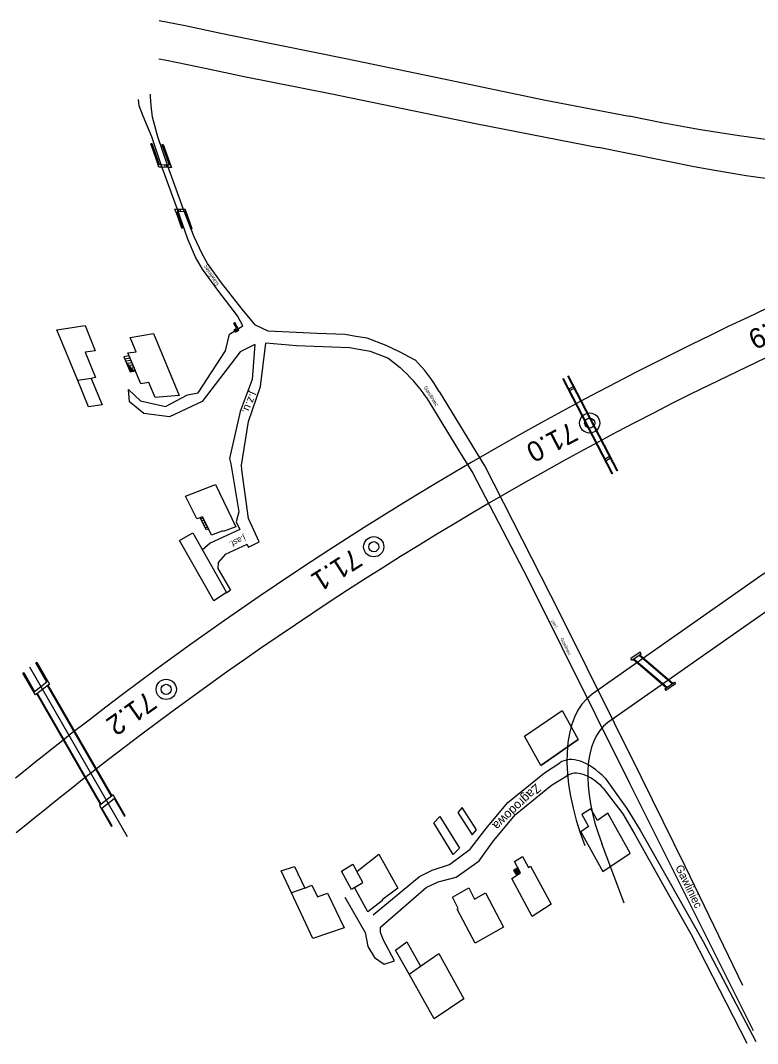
# Model space of a CAD drawing. Extents: x 6541740 to 6556805, y 5525233 to 5530361.
# Drawn here: x 6554814.6 to 6554888.2, y 5525643 to 5525745.1 of the extents above; entities that cross this region are included whole.
import ezdxf

# ---------------------------------------------------------------- set-up
doc = ezdxf.new("R2010")
doc.units = 0
for name, color, linetype in [('Default', 7, 'Continuous'), ('TOR_SCH-budynki', 7, 'Continuous'), ('TOR_SCH-hektometry', 7, 'Continuous'), ('TOR_SCH-obiekty projektowane', 7, 'Continuous'), ('TOR_SCH-przejazdy+drogi istniejace', 7, 'Continuous'), ('TOR_SCH-przejazdy+drogi projektowane', 7, 'Continuous'), ('TOR_SCH-tory i rozjazdy do rozbiorki', 7, 'Continuous'), ('TOR_SCH-tory projektowane', 7, 'Continuous')]:
    doc.layers.add(name, color=color, linetype=linetype)

# ---------------------------------------------------------------- blocks, each defined once
blk = doc.blocks.new('4010_1')
at = {"layer": 'Default'}
for radius in [0.75, 0.375]:
    blk.add_circle((0, 0), radius, dxfattribs=at)
blk = doc.blocks.new('POINT_DISPLAY')
at = {"layer": 'Default'}
blk.add_line((0, 0), (0, 0), dxfattribs=at)

msp = doc.modelspace()

# ---------------------------------------------------------------- linework, layer by layer
at = {"layer": 'TOR_SCH-budynki'}
for p, q in [((6554818.21, 5525714.25), (6554821.01, 5525714.68)), ((6554821.01, 5525714.68), (6554822.01, 5525712.18)), ((6554820.28, 5525709.22), (6554818.21, 5525714.25)), ((6554825.53, 5525713.5), (6554827.85, 5525713.88)), ((6554827.85, 5525713.88), (6554830.42, 5525707.7)), ((6554826.12, 5525712.08), (6554825.53, 5525713.5)), ((6554822.01, 5525712.18), (6554821.01, 5525712.03)), ((6554821.01, 5525712.03), (6554822.06, 5525709.49)), ((6554825.41, 5525711.66), (6554824.89, 5525711.58)), ((6554824.89, 5525711.58), (6554825.51, 5525710.07)), ((6554825.3, 5525711.95), (6554826.12, 5525712.08)), ((6554826.57, 5525708.88), (6554825.3, 5525711.95)), ((6554826.04, 5525710.16), (6554825.41, 5525711.66)), ((6554825.51, 5525711.44), (6554824.99, 5525711.35)), ((6554825.6, 5525711.21), (6554825.08, 5525711.12)), ((6554825.7, 5525710.98), (6554825.24, 5525710.9)), ((6554825.6, 5525710.09), (6554825.28, 5525710.87)), ((6554825.79, 5525710.75), (6554825.46, 5525710.7)), ((6554825.73, 5525710.11), (6554825.5, 5525710.66)), ((6554825.89, 5525710.52), (6554825.69, 5525710.49)), ((6554822.06, 5525709.49), (6554821.62, 5525709.42)), ((6554825.51, 5525710.07), (6554826.04, 5525710.16)), ((6554825.86, 5525710.13), (6554825.72, 5525710.45)), ((6554825.98, 5525710.29), (6554825.91, 5525710.28)), ((6554825.99, 5525710.15), (6554825.95, 5525710.24)), ((6554821.62, 5525709.42), (6554820.28, 5525709.22)), ((6554821.37, 5525706.57), (6554820.28, 5525709.22)), ((6554821.62, 5525709.42), (6554822.71, 5525706.77)), ((6554827.39, 5525709.02), (6554826.57, 5525708.88)), ((6554828.01, 5525707.51), (6554827.39, 5525709.02)), ((6554830.42, 5525707.7), (6554828.01, 5525707.51)), ((6554822.71, 5525706.77), (6554821.37, 5525706.57)), ((6554831.05, 5525697.67), (6554834.05, 5525698.83)), ((6554834.05, 5525698.83), (6554836.06, 5525694.61)), ((6554832.16, 5525695.39), (6554831.05, 5525697.67)), ((6554832.75, 5525695.61), (6554832.16, 5525695.39)), ((6554832.51, 5525695.52), (6554832.75, 5525695.61)), ((6554833.11, 5525694.29), (6554832.51, 5525695.52)), ((6554832.57, 5525695.41), (6554832.8, 5525695.5)), ((6554832.67, 5525695.19), (6554832.91, 5525695.28)), ((6554833.64, 5525693.77), (6554832.75, 5525695.61)), ((6554832.75, 5525695.61), (6554833.34, 5525694.38)), ((6554832.78, 5525694.96), (6554833.02, 5525695.05)), ((6554832.89, 5525694.74), (6554833.13, 5525694.83)), ((6554833, 5525694.51), (6554833.24, 5525694.6)), ((6554833.34, 5525694.38), (6554833.11, 5525694.29)), ((6554834.77, 5525694.2), (6554833.64, 5525693.77)), ((6554834.8, 5525694.14), (6554834.77, 5525694.2)), ((6554836.06, 5525694.61), (6554834.8, 5525694.14)), ((6554830.44, 5525693.22), (6554831.76, 5525694)), ((6554833.86, 5525687.21), (6554830.44, 5525693.22)), ((6554831.76, 5525694), (6554835.13, 5525688.03)), ((6554835.13, 5525688.03), (6554833.86, 5525687.21)), ((6554864.9, 5525673.69), (6554868.66, 5525676.25)), ((6554868.66, 5525676.25), (6554870.25, 5525673.37)), ((6554866.51, 5525670.76), (6554864.9, 5525673.69)), ((6554870.25, 5525673.37), (6554866.51, 5525670.76)), ((6554855.83, 5525665.05), (6554856.44, 5525665.68)), ((6554856.44, 5525665.68), (6554858.39, 5525662.52)), ((6554871.51, 5525666.45), (6554870.63, 5525665.87)), ((6554870.63, 5525665.87), (6554871.27, 5525664.68)), ((6554872.17, 5525665.27), (6554871.51, 5525666.45)), ((6554873.22, 5525666.01), (6554872.17, 5525665.27)), ((6554875.44, 5525662.02), (6554873.22, 5525666.01)), ((6554857.77, 5525661.88), (6554855.83, 5525665.05)), ((6554871.27, 5525664.68), (6554870.51, 5525664.14)), ((6554870.51, 5525664.14), (6554872.71, 5525660.18)), ((6554858.39, 5525662.52), (6554857.77, 5525661.88)), ((6554848.15, 5525660.18), (6554850.36, 5525661.92)), ((6554850.36, 5525661.92), (6554852.23, 5525658.54)), ((6554863.89, 5525661.17), (6554864.69, 5525661.68)), ((6554864.69, 5525661.68), (6554865.29, 5525660.59)), ((6554872.71, 5525660.18), (6554875.44, 5525662.02)), ((6554840.59, 5525660.25), (6554841.94, 5525660.67)), ((6554841.94, 5525660.67), (6554842.96, 5525658.51)), ((6554846.61, 5525660.21), (6554847.74, 5525660.93)), ((6554847.74, 5525660.93), (6554848.15, 5525660.18)), ((6554864.22, 5525660.57), (6554863.81, 5525660.31)), ((6554864.49, 5525660.07), (6554863.89, 5525661.17)), ((6554864.13, 5525660.52), (6554864.4, 5525660.01)), ((6554864.49, 5525660.07), (6554864.22, 5525660.57)), ((6554865.29, 5525660.59), (6554865.5, 5525660.72)), ((6554865.5, 5525660.72), (6554867.57, 5525656.93)), ((6554841.63, 5525658.05), (6554840.59, 5525660.25)), ((6554847.61, 5525658.39), (6554846.61, 5525660.21)), ((6554848.74, 5525659.1), (6554848.15, 5525660.18)), ((6554863.62, 5525659.5), (6554864.49, 5525660.07)), ((6554865.67, 5525655.7), (6554863.62, 5525659.5)), ((6554863.81, 5525660.31), (6554864.09, 5525659.81)), ((6554863.92, 5525660.38), (6554864.19, 5525659.87)), ((6554864.02, 5525660.45), (6554864.3, 5525659.94)), ((6554864.09, 5525659.81), (6554864.49, 5525660.07)), ((6554842.96, 5525658.51), (6554841.63, 5525658.05)), ((6554842.96, 5525658.51), (6554843.67, 5525658.82)), ((6554843.67, 5525658.82), (6554844.21, 5525657.65)), ((6554847.91, 5525658.58), (6554847.61, 5525658.39)), ((6554847.91, 5525658.58), (6554848.74, 5525659.1)), ((6554849.26, 5525656.17), (6554847.91, 5525658.58)), ((6554852.23, 5525658.54), (6554850.69, 5525657.36)), ((6554857.7, 5525657.61), (6554859.32, 5525658.56)), ((6554859.32, 5525658.56), (6554859.91, 5525657.43)), ((6554843.77, 5525653.51), (6554841.63, 5525658.05)), ((6554844.21, 5525657.65), (6554845.22, 5525658.03)), ((6554845.22, 5525658.03), (6554846.87, 5525654.57)), ((6554858.27, 5525656.51), (6554857.7, 5525657.61)), ((6554859.91, 5525657.43), (6554861.01, 5525658.07)), ((6554861.01, 5525658.07), (6554862.81, 5525654.64)), ((6554850.72, 5525657.3), (6554849.26, 5525656.17)), ((6554850.69, 5525657.36), (6554850.72, 5525657.3)), ((6554858.16, 5525656.42), (6554858.27, 5525656.51)), ((6554859.96, 5525653.03), (6554858.16, 5525656.42)), ((6554867.57, 5525656.93), (6554865.67, 5525655.7)), ((6554846.87, 5525654.57), (6554843.77, 5525653.51)), ((6554862.81, 5525654.64), (6554859.96, 5525653.03)), ((6554852.01, 5525652.35), (6554853.14, 5525653.18)), ((6554853.38, 5525649.94), (6554852.01, 5525652.35)), ((6554853.14, 5525653.18), (6554854.51, 5525650.74)), ((6554854.51, 5525650.74), (6554856.34, 5525652.01)), ((6554856.34, 5525652.01), (6554858.84, 5525647.48)), ((6554853.38, 5525649.94), (6554854.51, 5525650.74)), ((6554855.87, 5525645.47), (6554853.38, 5525649.94)), ((6554858.84, 5525647.48), (6554855.87, 5525645.47))]:
    msp.add_line(p, q, dxfattribs=at)
msp.add_lwpolyline([(6554858.23, 5525666.08), (6554859.66, 5525663.86), (6554860.1, 5525664.36), (6554858.66, 5525666.58)], close=True, dxfattribs=at)
at = {"layer": 'TOR_SCH-obiekty projektowane'}
for p, q in [((6554825.24, 5525663.66), (6554815.49, 5525680.57)), ((6554822.57, 5525666.86), (6554816.2, 5525677.91)), ((6554822.63, 5525666.9), (6554816.26, 5525677.95)), ((6554823.65, 5525667.71), (6554817.28, 5525678.76)), ((6554823.71, 5525667.75), (6554817.34, 5525678.8))]:
    msp.add_line(p, q, dxfattribs=at)
for points in [[(6554869.18, 5525709.66), (6554874.1, 5525700.19)], [(6554869.25, 5525709.7), (6554874.17, 5525700.23)], [(6554868.67, 5525709.4), (6554873.61, 5525699.9)], [(6554868.74, 5525709.43), (6554873.67, 5525699.93)], [(6554869.81, 5525708.6), (6554869.24, 5525708.3)], [(6554869.75, 5525708.72), (6554869.68, 5525708.69)], [(6554869.23, 5525708.46), (6554869.17, 5525708.43)], [(6554869.91, 5525708.43), (6554869.33, 5525708.13)], [(6554873.43, 5525701.64), (6554872.87, 5525701.31)], [(6554873.52, 5525701.47), (6554872.97, 5525701.13)], [(6554873.67, 5525699.93), (6554873.61, 5525699.9)], [(6554874.17, 5525700.23), (6554874.1, 5525700.19)], [(6554875.6, 5525681.27), (6554876.55, 5525681.93), (6554876.45, 5525682.1), (6554875.5, 5525681.44)], [(6554875.6, 5525681.27), (6554875.6, 5525681.27), (6554875.5, 5525681.44)], [(6554875.75, 5525681.37), (6554879.06, 5525678.53)], [(6554875.82, 5525681.42), (6554879.13, 5525678.59)], [(6554876.33, 5525681.77), (6554879.64, 5525678.94)], [(6554876.41, 5525681.83), (6554879.71, 5525678.99)], [(6554878.91, 5525678.43), (6554879.86, 5525679.1), (6554879.96, 5525678.92), (6554879.01, 5525678.26)], [(6554878.91, 5525678.43), (6554878.91, 5525678.43), (6554879.01, 5525678.26)]]:
    msp.add_lwpolyline(points, dxfattribs=at)
for points in [[(6554817.2, 5525679.13), (6554816.11, 5525681.01), (6554816.19, 5525681.07), (6554817.45, 5525678.89), (6554816.07, 5525677.81), (6554814.81, 5525679.99), (6554814.89, 5525680.06), (6554815.98, 5525678.17)], [(6554823.91, 5525667.48), (6554824.94, 5525665.7), (6554825.02, 5525665.76), (6554823.82, 5525667.84), (6554822.44, 5525666.76), (6554823.64, 5525664.68), (6554823.72, 5525664.74), (6554822.69, 5525666.52)]]:
    msp.add_lwpolyline(points, close=True, dxfattribs=at)
at = {"layer": 'TOR_SCH-przejazdy+drogi istniejace'}
for p, q in [((6554827.73, 5525732.82), (6554827.59, 5525732.82)), ((6554827.84, 5525732.11), (6554827.59, 5525732.82)), ((6554827.75, 5525732.77), (6554827.73, 5525732.82)), ((6554828.34, 5525731.03), (6554827.75, 5525732.77)), ((6554828.67, 5525732.78), (6554828.81, 5525732.78)), ((6554828.93, 5525732.07), (6554829.13, 5525731.88)), ((6554828.15, 5525731.61), (6554827.95, 5525731.79)), ((6554828.23, 5525731.37), (6554828.03, 5525731.55)), ((6554829.02, 5525731.8), (6554829.22, 5525731.62)), ((6554828.98, 5525730.71), (6554828.93, 5525730.49)), ((6554829.18, 5525730.71), (6554829.12, 5525730.48)), ((6554830.33, 5525726.27), (6554830.28, 5525726.04)), ((6554830.52, 5525726.28), (6554830.47, 5525726.04)), ((6554830.38, 5525725.52), (6554830.77, 5525724.44)), ((6554830.39, 5525725.13), (6554830.58, 5525724.96)), ((6554830.47, 5525724.89), (6554830.67, 5525724.71)), ((6554831.38, 5525725.27), (6554831.18, 5525725.45)), ((6554831.46, 5525725.01), (6554831.26, 5525725.2)), ((6554830.63, 5525724.44), (6554830.77, 5525724.44)), ((6554831.7, 5525724.33), (6554831.56, 5525724.34)), ((6554835.43, 5525713.82), (6554836.76, 5525714.65)), ((6554835.96, 5525714.99), (6554835.86, 5525714.91)), ((6554836.02, 5525714.89), (6554835.91, 5525714.95)), ((6554836.2, 5525714.58), (6554835.97, 5525714.72)), ((6554835.05, 5525712.15), (6554835.43, 5525713.82)), ((6554836.02, 5525714.04), (6554835.9, 5525714.26)), ((6554844.2, 5525713.9), (6554839.31, 5525714.13)), ((6554837.98, 5525712.79), (6554836.51, 5525712.08)), ((6554837.98, 5525712.79), (6554837.69, 5525709.32)), ((6554838.54, 5525708.6), (6554839.05, 5525712.93)), ((6554832.31, 5525707.96), (6554835.05, 5525712.15)), ((6554836.51, 5525712.08), (6554832.7, 5525707.11)), ((6554837.69, 5525709.32), (6554836.5, 5525706.1)), ((6554837.34, 5525705.1), (6554838.54, 5525708.6)), ((6554825.46, 5525707.07), (6554825.35, 5525708.32)), ((6554825.35, 5525708.32), (6554826.55, 5525707.19)), ((6554829.03, 5525706.6), (6554831.24, 5525707.78)), ((6554831.24, 5525707.78), (6554832.31, 5525707.96)), ((6554855.08, 5525707.55), (6554858.31, 5525702.25)), ((6554860.94, 5525700.7), (6554856.39, 5525708.1)), ((6554826.87, 5525705.91), (6554825.46, 5525707.07)), ((6554826.55, 5525707.19), (6554829.03, 5525706.6)), ((6554832.7, 5525707.11), (6554829.43, 5525705.57)), ((6554829.43, 5525705.57), (6554826.87, 5525705.91)), ((6554836.5, 5525706.1), (6554835.45, 5525701.41)), ((6554836.65, 5525700.75), (6554837.34, 5525705.1)), ((6554835.45, 5525701.41), (6554835.57, 5525700.87)), ((6554858.31, 5525702.25), (6554859.73, 5525699.95)), ((6554835.57, 5525700.87), (6554836.37, 5525696.08)), ((6554836.66, 5525700.29), (6554836.65, 5525700.75)), ((6554868.44, 5525685.92), (6554860.94, 5525700.7)), ((6554837.32, 5525695.44), (6554836.66, 5525700.29)), ((6554859.73, 5525699.95), (6554865.22, 5525689.42)), ((6554836.37, 5525696.08), (6554836.09, 5525695.08)), ((6554838.4, 5525693.11), (6554837.32, 5525695.44)), ((6554836.09, 5525695.08), (6554836.46, 5525694.34)), ((6554837.18, 5525692.84), (6554837.32, 5525692.56)), ((6554837.32, 5525692.56), (6554838.4, 5525693.11)), ((6554865.22, 5525689.42), (6554875.39, 5525669)), ((6554876.58, 5525669.58), (6554868.44, 5525685.92)), ((6554866.51, 5525670.76), (6554870.25, 5525673.37)), ((6554875.39, 5525669), (6554887.71, 5525644.33)), ((6554880.95, 5525660.72), (6554876.58, 5525669.58)), ((6554886.68, 5525648.8), (6554880.95, 5525660.72)), ((6554887.13, 5525643.01), (6554881.67, 5525653.67)), ((6554882.72, 5525653.19), (6554887.99, 5525643.21))]:
    msp.add_line(p, q, dxfattribs=at)
for points in [[(6554828.62, 5525730.72), (6554827.67, 5525733.52), (6554826.81, 5525735.58), (6554826.43, 5525736.62), (6554826.34, 5525737.25)], [(6554830.84, 5525726.29), (6554829.23, 5525730.71), (6554828.28, 5525733.53), (6554827.75, 5525735.49), (6554827.62, 5525736.66), (6554827.55, 5525737.55), (6554827.55, 5525737.78)], [(6554828.54, 5525730.5), (6554828.37, 5525730.5), (6554828.21, 5525731.04), (6554827.84, 5525732.11)], [(6554828.67, 5525732.78), (6554829.31, 5525731), (6554829.34, 5525730.91)], [(6554828.81, 5525732.78), (6554829.45, 5525731), (6554829.48, 5525730.9)], [(6554829.34, 5525730.91), (6554829.42, 5525730.7), (6554829.23, 5525730.71), (6554828.62, 5525730.72), (6554828.44, 5525730.73), (6554828.35, 5525731.02), (6554828.34, 5525731.03)], [(6554829.48, 5525730.9), (6554829.64, 5525730.47), (6554829.31, 5525730.48), (6554828.71, 5525730.49), (6554828.54, 5525730.5)], [(6554836.76, 5525714.65), (6554836.25, 5525715.67), (6554834.26, 5525718.22), (6554832.75, 5525720.33), (6554832.05, 5525721.53), (6554831.27, 5525723.31), (6554830.25, 5525726.27), (6554828.62, 5525730.72)], [(6554831.09, 5525726.13), (6554831.03, 5525726.29), (6554830.84, 5525726.29), (6554830.25, 5525726.27), (6554829.96, 5525726.26), (6554830.04, 5525726.07)], [(6554830.04, 5525726.07), (6554830.13, 5525725.87), (6554830.63, 5525724.44)], [(6554830.97, 5525726.06), (6554830.97, 5525726.06), (6554830.92, 5525726.06), (6554830.33, 5525726.04), (6554830.19, 5525726.04), (6554830.26, 5525725.88), (6554830.38, 5525725.52)], [(6554839.31, 5525714.13), (6554838.04, 5525714.72), (6554836.83, 5525716.15), (6554834.65, 5525718.94), (6554833.25, 5525720.9), (6554832.7, 5525721.85), (6554831.92, 5525723.55), (6554830.84, 5525726.29)], [(6554831.56, 5525724.34), (6554830.98, 5525726.06), (6554830.97, 5525726.06)], [(6554831.7, 5525724.33), (6554831.11, 5525726.05), (6554831.09, 5525726.13)], [(6554835.9, 5525714.26), (6554836.15, 5525714.42), (6554835.86, 5525714.91)], [(6554836.02, 5525714.04), (6554836.38, 5525714.27), (6554835.96, 5525714.99)], [(6554848.06, 5525713.61), (6554846.98, 5525713.79), (6554844.2, 5525713.9)], [(6554853.96, 5525711.25), (6554852.42, 5525712.06), (6554851.09, 5525712.69), (6554849.19, 5525713.42), (6554848.06, 5525713.61)], [(6554848.91, 5525712.2), (6554847.42, 5525712.45), (6554842.14, 5525712.66), (6554839.05, 5525712.93)], [(6554852.47, 5525710.48), (6554851.25, 5525711.43), (6554849.53, 5525712.09), (6554848.91, 5525712.2)], [(6554836.46, 5525694.34), (6554833.49, 5525692.96), (6554832.72, 5525692.25)], [(6554837.18, 5525692.84), (6554835, 5525691.83), (6554834.29, 5525691.02)], [(6554834.29, 5525691.02), (6554834.27, 5525690.45), (6554835.54, 5525688.26), (6554835.14, 5525687.99)], [(6554849.78, 5525655.86), (6554854.42, 5525659.69), (6554855.67, 5525660.31), (6554857.39, 5525660.89), (6554859.48, 5525662.43), (6554861.03, 5525664.45), (6554863.24, 5525667.07), (6554866.9, 5525670.03), (6554868.41, 5525671.02)], [(6554850.5, 5525654.64), (6554855.08, 5525658.58), (6554856.28, 5525659.17), (6554858.06, 5525659.62), (6554860.35, 5525661.24), (6554861.78, 5525663.26), (6554863.98, 5525665.87), (6554867.59, 5525668.79), (6554869.12, 5525669.74)], [(6554872.95, 5525669.49), (6554875.12, 5525666.49), (6554876.43, 5525664.3)], [(6554872.75, 5525668.52), (6554874.7, 5525665.94), (6554875.88, 5525663.96)], [(6554875.88, 5525663.96), (6554878.96, 5525658.43), (6554881.67, 5525653.67)], [(6554876.43, 5525664.3), (6554879.57, 5525658.78), (6554882.72, 5525653.19)], [(6554846.96, 5525657.62), (6554848.99, 5525654.09), (6554849.26, 5525652.71), (6554849.93, 5525651.61), (6554850.89, 5525650.93), (6554851.9, 5525651.28), (6554850.8, 5525653.32), (6554850.53, 5525654.1), (6554850.5, 5525654.64)]]:
    msp.add_lwpolyline(points, dxfattribs=at)
for centre, major_axis, ratio, start_param, end_param in [((6554852.9, 5525705.1), (-4.12, 8.02), 0.5, 4.832479, 5.298873), ((6554851.82, 5525702.59), (-4.91, 9.56), 0.5, 4.988219, 5.389009), ((6554871.95, 5525664.67), (3.33, -6.48), 0.499934, 2.12454, 3.208877), ((6554871.95, 5525664.67), (-2.66, 5.17), 0.499897, 5.265078, 6.351543)]:
    msp.add_ellipse(centre, major_axis=major_axis, ratio=ratio, start_param=start_param, end_param=end_param, dxfattribs=at)
at = {"layer": 'TOR_SCH-przejazdy+drogi projektowane'}
for p, q in [((6554888.16, 5525689.46), (6554871.64, 5525677.88)), ((6554889.74, 5525686.63), (6554873.22, 5525675.05)), ((6554874.86, 5525657.04), (6554872.6, 5525662.99))]:
    msp.add_line(p, q, dxfattribs=at)
for centre, major_axis, start_param, end_param in [((6554986.22, 5525513.69), (-92.12, 179.35), 6.132043, 6.351843), ((6554879.73, 5525663.39), (-7.6, 14.79), 0.068658, 1.35885), ((6554879.73, 5525663.39), (-6.11, 11.9), 0.068658, 1.352443)]:
    msp.add_ellipse(centre, major_axis=major_axis, ratio=0.5, start_param=start_param, end_param=end_param, dxfattribs=at)
at = {"layer": 'TOR_SCH-tory i rozjazdy do rozbiorki'}
for points in [[(6554828.42, 5525745.15), (6554831, 5525744.64), (6554834.57, 5525743.87), (6554837.5, 5525743.27)], [(6554837.5, 5525743.27), (6554847.04, 5525741.34), (6554856.68, 5525739.36), (6554866.82, 5525737.22), (6554875.34, 5525735.59)], [(6554828.39, 5525741.32), (6554829.15, 5525741.17), (6554833.02, 5525740.37), (6554836.91, 5525739.55)], [(6554836.91, 5525739.55), (6554845.48, 5525737.85), (6554860.15, 5525734.83), (6554872.27, 5525732.46)], [(6554889.23, 5525733.23), (6554887.3, 5525733.49), (6554886.34, 5525733.62), (6554884.41, 5525733.92), (6554882.47, 5525734.24), (6554881.18, 5525734.46), (6554878.59, 5525734.94), (6554878.59, 5525734.94), (6554877.15, 5525735.22), (6554875.34, 5525735.59)], [(6554889.91, 5525729.22), (6554887.98, 5525729.5), (6554887.01, 5525729.65), (6554885.07, 5525729.97), (6554883.12, 5525730.31), (6554881.82, 5525730.55), (6554879.22, 5525731.05), (6554879.22, 5525731.05), (6554874.9, 5525731.92), (6554872.27, 5525732.46)]]:
    msp.add_lwpolyline(points, dxfattribs=at)
at = {"layer": 'TOR_SCH-tory projektowane'}
for points in [[(6554819.74, 5525674.02), (6554818.79, 5525673.27), (6554817.85, 5525672.53), (6554816.9, 5525671.78), (6554815.96, 5525671.03), (6554815.02, 5525670.27), (6554814.08, 5525669.51)], [(6554821.69, 5525670.07), (6554820.74, 5525669.33), (6554819.79, 5525668.58), (6554818.85, 5525667.83), (6554817.9, 5525667.08), (6554816.96, 5525666.32), (6554816.02, 5525665.57), (6554815.09, 5525664.8), (6554814.15, 5525664.04)]]:
    msp.add_lwpolyline(points, dxfattribs=at)
for centre, major_axis, start_param, end_param in [((6555516.78, 5524462.45), (-640.8, 1247.55), 6.188263, 6.378108), ((6555517.43, 5524460.63), (-639.66, 1245.32), 6.188355, 6.378016)]:
    msp.add_ellipse(centre, major_axis=major_axis, ratio=0.5, start_param=start_param, end_param=end_param, dxfattribs=at)

# ---------------------------------------------------------------- block references
at = {"layer": 'TOR_SCH-budynki', "xscale": 0.287479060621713, "yscale": 0.4348142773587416, "rotation": -7.56870530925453}
msp.add_blockref('POINT_DISPLAY', (6554863.81, 5525660.31), dxfattribs=at)
at = {"layer": 'TOR_SCH-hektometry', "xscale": 1.345963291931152, "yscale": 1.3459632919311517, "rotation": 8.951820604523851}
for p in [(6554871.4, 5525704.96), (6554849.84, 5525692.61), (6554829.12, 5525678.37)]:
    msp.add_blockref('4010_1', p, dxfattribs=at)

# ---------------------------------------------------------------- texts
at = {"layer": 'TOR_SCH-hektometry'}
for s, rotation, p in [('70.9', 206.1678, (6554891.71, 5525716.31)), ('71.0', 207.573, (6554869.49, 5525705.12)), ('71.1', 212.4846, (6554847.8, 5525692.52)), ('71.2', 215.3311, (6554827.2, 5525678.27))]:
    msp.add_text(s, height=2, rotation=rotation, dxfattribs=at).set_placement(p)
at = {"layer": 'TOR_SCH-przejazdy+drogi istniejace'}
for s, height, rotation, p in [('Gawliniec', 0.394, 122.9792, (6554834.4, 5525718.81)), ('Gawliniec', 0.378, 302.3103, (6554854.81, 5525708.5)), ('j.z.u.', 0.8, 246.6103, (6554837.57, 5525708.15)), ('j.asf.', 0.6, 204.9536, (6554836.88, 5525693.78)), ('j.asf.', 0.313, 116.8118, (6554868.14, 5525684.58)), ('Gawliniec', 0.315, 296.3467, (6554868.47, 5525683.42)), ('Zagrodowa', 0.9, 223.3314, (6554866.01, 5525669.01)), ('Gawliniec', 0.8, 296.0494, (6554879.93, 5525660.61))]:
    msp.add_text(s, height=height, rotation=rotation, dxfattribs=at).set_placement(p)

doc.saveas('drawing.dxf')
